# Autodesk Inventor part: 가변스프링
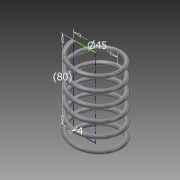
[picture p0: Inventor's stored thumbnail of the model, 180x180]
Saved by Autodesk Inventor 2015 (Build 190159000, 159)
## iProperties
Created: 2016-02
Part Number: 가변스프링
Material: 스테인레스 스틸
Document SubType Name: Modeling
Designer: Administrator
Mass: 84.1995 g
Surface Area: 106.448 cm^2
Volume: 10.5249 cm^3
Density: 8 g/cm^3
Appearance: 반연마
Author: Administrator
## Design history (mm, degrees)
sketch "스케치1"
  geometry: L1 (0, 0)-(22.5, 0); L2 (22.5, 0)-(22.5, 67.25); L3 (22.5, 67.25)-(0, 67.25); L4 (0, 67.25)-(0, 0); C1 r 2 at (22.5, 0)
  constraints: 8 end point, 2 parallel, 1 centre point, 1 coincident, 1 horizontal, 1 perpendicular
  dimensions: "d0" = 45 diameter of L2 L4; "d1" = 67.25 distance of L1.end L2.end (derived); "d2" = 4 diameter of C1
feature "코일1" sketch "스케치1" pitch "d3" = 10; turns "d5" = 6; dims "d4" = 67.25 (= d1), "d6" = 0, angle "d7" = 90 deg, angle "d8" = 90 deg, "d9" = 0, "d10" = 0
sketch "스케치2"
  geometry: L1 (-20.5, 0)-(-24.5, 0) reference; 1 further point
  constraints: 1 horizontal alignment
extrude "돌출1" cut sketch "스케치2" stored distance "d11" = 10; taper "d12" = 0 deg
node "작업 평면1"
sketch "스케치3"
  geometry: L1 (20.5, 0)-(24.5, 0) reference; 1 further point
  constraints: 1 horizontal alignment
extrude "돌출2" cut sketch "스케치3" stored distance "d13" = 10; taper "d14" = 0 deg
node "솔리드1"
node "절단 모서리 투영1"
node "절단 모서리 투영2"
